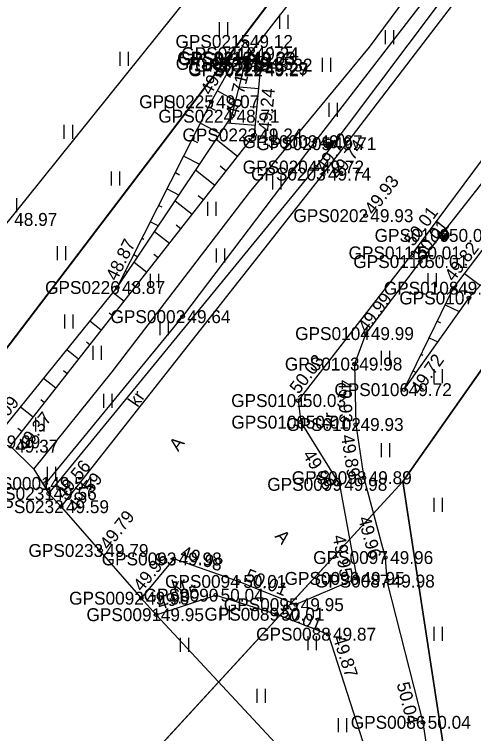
# Model space of a CAD drawing. Extents: x 563121 to 567545, y 6570841 to 6581299.
# Drawn here: x 565782.48 to 565807.43, y 6571805.07 to 6571844.15 of the extents above; entities that cross this region are included whole.
import ezdxf

# ---------------------------------------------------------------- set-up
doc = ezdxf.new("R2010")
doc.units = 0
for name, color, linetype in [('HALJASTUS', 7, 'Continuous'), ('KORGUS-EH2000', 7, 'Continuous'), ('MOOTKORG-EH2000', 7, 'Continuous'), ('MOOTMPUNKT', 7, 'Continuous'), ('MOOTNR', 7, 'Continuous'), ('MOOTPIIR', 7, 'Continuous'), ('PIIR', 7, 'Continuous'), ('POST', 7, 'Continuous'), ('RELJEEF', 7, 'Continuous'), ('SITRASS', 7, 'Continuous'), ('TEE', 7, 'Continuous'), ('TRUUP', 7, 'Continuous')]:
    doc.layers.add(name, color=color, linetype=linetype)

msp = doc.modelspace()

# ---------------------------------------------------------------- linework, layer by layer
at = {"layer": 'HALJASTUS'}
for p, q in [((565796.879, 6571844.119), (565796.879, 6571843.357)), ((565797.334, 6571844.119), (565797.334, 6571843.357)), ((565793.597, 6571843.716), (565793.597, 6571842.955)), ((565794.052, 6571843.716), (565794.052, 6571842.955)), ((565802.616, 6571843.299), (565802.616, 6571842.538)), ((565803.071, 6571843.299), (565803.071, 6571842.538)), ((565788.204, 6571842.119), (565788.204, 6571841.358)), ((565788.659, 6571842.119), (565788.659, 6571841.358)), ((565799.2, 6571841.795), (565799.2, 6571841.034)), ((565799.655, 6571841.795), (565799.655, 6571841.034)), ((565790.667, 6571839.664), (565790.667, 6571838.903)), ((565791.122, 6571839.664), (565791.122, 6571838.903)), ((565799.557, 6571839.345), (565799.557, 6571838.583)), ((565800.012, 6571839.345), (565800.012, 6571838.583)), ((565785.173, 6571838.143), (565785.173, 6571837.382)), ((565785.628, 6571838.143), (565785.628, 6571837.382)), ((565796.096, 6571837.876), (565796.096, 6571837.115)), ((565796.551, 6571837.876), (565796.551, 6571837.115)), ((565787.738, 6571835.612), (565787.738, 6571834.851)), ((565788.193, 6571835.612), (565788.193, 6571834.851)), ((565796.498, 6571835.39), (565796.498, 6571834.628)), ((565796.953, 6571835.39), (565796.953, 6571834.628)), ((565782.597, 6571834.166), (565782.597, 6571833.405)), ((565792.978, 6571833.966), (565792.978, 6571833.205)), ((565793.433, 6571833.966), (565793.433, 6571833.205)), ((565784.809, 6571831.56), (565784.809, 6571830.799)), ((565785.264, 6571831.56), (565785.264, 6571830.799)), ((565793.439, 6571831.435), (565793.439, 6571830.674)), ((565793.894, 6571831.435), (565793.894, 6571830.674)), ((565789.861, 6571830.057), (565789.861, 6571829.296)), ((565790.316, 6571830.057), (565790.316, 6571829.296)), ((565804.948, 6571830.093), (565804.948, 6571829.332)), ((565805.403, 6571830.093), (565805.403, 6571829.332)), ((565785.198, 6571827.84), (565785.198, 6571827.079)), ((565785.653, 6571827.84), (565785.653, 6571827.079)), ((565790.38, 6571827.48), (565790.38, 6571826.719)), ((565790.835, 6571827.48), (565790.835, 6571826.719)), ((565786.743, 6571826.148), (565786.743, 6571825.387)), ((565787.199, 6571826.148), (565787.199, 6571825.387)), ((565802.404, 6571825.86), (565802.404, 6571825.099)), ((565802.859, 6571825.86), (565802.859, 6571825.099)), ((565805.272, 6571824.881), (565805.272, 6571824.119)), ((565805.728, 6571824.881), (565805.728, 6571824.119)), ((565787.32, 6571823.525), (565787.32, 6571822.764)), ((565787.775, 6571823.525), (565787.775, 6571822.764)), ((565783.626, 6571822.239), (565783.626, 6571821.478)), ((565784.081, 6571822.239), (565784.081, 6571821.478)), ((565802.404, 6571820.86), (565802.404, 6571820.099)), ((565802.859, 6571820.86), (565802.859, 6571820.099)), ((565784.261, 6571819.57), (565784.261, 6571818.809)), ((565784.716, 6571819.57), (565784.716, 6571818.809)), ((565805.272, 6571817.881), (565805.272, 6571817.119)), ((565805.728, 6571817.881), (565805.728, 6571817.119)), ((565793.701, 6571812.012), (565793.701, 6571811.251)), ((565794.157, 6571812.012), (565794.157, 6571811.251)), ((565805.272, 6571810.881), (565805.272, 6571810.119)), ((565805.728, 6571810.881), (565805.728, 6571810.119)), ((565791.49, 6571810.282), (565791.49, 6571809.521)), ((565791.945, 6571810.282), (565791.945, 6571809.521)), ((565798.42, 6571810.359), (565798.42, 6571809.598)), ((565798.876, 6571810.359), (565798.876, 6571809.598)), ((565795.645, 6571807.502), (565795.645, 6571806.74)), ((565796.1, 6571807.502), (565796.1, 6571806.74)), ((565800.068, 6571805.911), (565800.068, 6571805.15)), ((565800.523, 6571805.911), (565800.523, 6571805.15))]:
    msp.add_line(p, q, dxfattribs=at)
at = {"layer": 'KORGUS-EH2000'}
for centre in [(565793.178, 6571839.402), (565794.289, 6571838.617), (565795.529, 6571837.598), (565798.874, 6571835.854), (565799.254, 6571835.472), (565801.558, 6571833.212), (565804.137, 6571831.188), (565804.535, 6571830.717), (565788.065, 6571829.31), (565806.328, 6571829.271), (565807.174, 6571828.74), (565801.583, 6571826.805), (565803.644, 6571823.76), (565797.898, 6571823.166), (565801.025, 6571821.866), (565801.467, 6571818.976), (565800.139, 6571818.615), (565784.347, 6571818.115), (565785.017, 6571817.401), (565787.162, 6571815.021), (565802.633, 6571814.638), (565791.141, 6571814.563), (565801.078, 6571813.504), (565794.654, 6571813.34), (565789.374, 6571812.429), (565790.175, 6571811.534), (565796.721, 6571811.558), (565799.531, 6571810.473), (565804.674, 6571805.685)]:
    msp.add_circle(centre, 0.1, dxfattribs=at)
at = {"layer": 'MOOTMPUNKT'}
for centre in [(565795.011, 6571842.678), (565795.327, 6571842.011), (565795.106, 6571841.78), (565795.165, 6571841.732), (565795.026, 6571841.487), (565795.832, 6571841.206), (565796.074, 6571841.393), (565795.847, 6571841.134), (565793.178, 6571839.402), (565794.289, 6571838.617), (565795.529, 6571837.598), (565798.797, 6571837.231), (565799.543, 6571837.122), (565798.874, 6571835.854), (565799.254, 6571835.472), (565801.558, 6571833.212), (565805.83, 6571832.14), (565804.137, 6571831.188), (565804.535, 6571830.717), (565788.065, 6571829.31), (565806.328, 6571829.271), (565807.174, 6571828.74), (565791.619, 6571827.726), (565801.583, 6571826.805), (565800.955, 6571825.15), (565803.644, 6571823.76), (565797.898, 6571823.166), (565798.048, 6571821.994), (565801.025, 6571821.866), (565801.467, 6571818.976), (565784.171, 6571818.664), (565800.139, 6571818.615), (565784.347, 6571818.115), (565785.017, 6571817.401), (565787.162, 6571815.021), (565802.633, 6571814.638), (565791.141, 6571814.563), (565801.078, 6571813.504), (565794.654, 6571813.34), (565802.718, 6571813.36), (565789.374, 6571812.429), (565793.422, 6571812.595), (565797.777, 6571812.08), (565790.175, 6571811.534), (565796.721, 6571811.558), (565799.531, 6571810.473), (565804.674, 6571805.685)]:
    msp.add_circle(centre, 0.1, dxfattribs=at)
at = {"layer": 'MOOTPIIR'}
msp.add_lwpolyline([(565823.283, 6571871.288), (565820.939, 6571873.864), (565815.364, 6571875.639), (565813.463, 6571874.16), (565808.89, 6571868.083), (565802.021, 6571858.377), (565795.67, 6571849.773), (565782.207, 6571833.008), (565776.308, 6571825.832), (565781.278, 6571820.922), (565782.262, 6571820.691), (565783.542, 6571819.443), (565784.347, 6571818.115), (565785.017, 6571817.401), (565789.374, 6571812.429), (565790.175, 6571811.534), (565801.221, 6571799.668)], dxfattribs=at)
at = {"layer": 'PIIR'}
for points in [[(566138.88, 6572289.1), (566071.95, 6572189.53), (566056.92, 6572168.48), (566043.44, 6572149.59), (566020.47, 6572117.41), (565845.87, 6571876.56), (565833.02, 6571860.66), (565803.59, 6571818.77), (565766.84, 6571778.8), (565712.27, 6571733.72), (565636.36, 6571689.97), (565561.65, 6571658.97), (565400, 6571600), (565315, 6571572), (565230, 6571552), (564980, 6571552), (564921.56, 6571543.26)], [(564959.63, 6571567.88), (565247.22, 6571575.87), (565310, 6571592), (565385.09, 6571617.94), (565603.34, 6571696.36), (565663.71, 6571724.88), (565720.01, 6571762.52), (565767.05, 6571806.3), (565831.51, 6571891.07), (565894.85, 6571978.6), (565929.68, 6572026.82), (566028.25, 6572163.26), (566043.71, 6572184.75), (566068.58, 6572219.3), (566114.67, 6572283.35)]]:
    msp.add_lwpolyline(points, dxfattribs=at)
for points in [[(565385.09, 6571617.94), (565348.3, 6571706.93), (565808.88, 6572174.3), (565817.95, 6572187.54), (565914.67, 6572223.63), (565927.34, 6572201.79), (566013.66, 6572213.36), (566028.25, 6572163.26), (565929.68, 6572026.82), (565869.35, 6572071.5), (565833.75, 6572019.48), (565773.79, 6571931.89), (565831.51, 6571891.07), (565767.05, 6571806.3), (565720.01, 6571762.52), (565663.71, 6571724.88), (565603.34, 6571696.36)], [(565833.02, 6571860.66), (565851.06, 6571859.65), (565901.01, 6571846.54), (565960.44, 6571833.78), (565973.49, 6571828.72), (566023.53, 6571796.39), (566089.86, 6571753.57), (566110.96, 6571742.32), (566147.53, 6571725.81), (566160.83, 6571717.7), (565835.49, 6571610.61), (565803.59, 6571818.77)], [(565803.59, 6571818.77), (565835.49, 6571610.61), (565859.22, 6571454.59), (565609.76, 6571322.76), (565540, 6571330), (565490, 6571465), (565440, 6571540), (565400, 6571600), (565561.65, 6571658.97), (565636.36, 6571689.97), (565712.27, 6571733.72), (565766.84, 6571778.8)]]:
    msp.add_lwpolyline(points, close=True, dxfattribs=at)
at = {"layer": 'POST'}
for p, q in [((565799.366, 6571836.946), (565799.719, 6571837.299)), ((565805.653, 6571831.964), (565806.007, 6571832.317))]:
    msp.add_line(p, q, dxfattribs=at)
for centre in [(565799.543, 6571837.122), (565805.83, 6571832.14)]:
    msp.add_circle(centre, 0.25, dxfattribs=at)
for centre, radius, start, end in [((565799.543, 6571837.122), 0.225, 224.8541, 45.0356), ((565799.543, 6571837.122), 0.2, 224.8427, 45.047), ((565799.543, 6571837.122), 0.175, 224.8281, 45.0616), ((565799.543, 6571837.122), 0.15, 224.8087, 45.081), ((565799.543, 6571837.122), 0.125, 224.7814, 45.1083), ((565799.543, 6571837.122), 0.1, 224.7406, 45.1491), ((565799.543, 6571837.122), 0.075, 224.6725, 45.2172), ((565799.543, 6571837.122), 0.05, 224.5363, 45.3534), ((565799.543, 6571837.122), 0.025, 224.1278, 45.7619), ((565805.83, 6571832.14), 0.225, 224.8541, 45.0356), ((565805.83, 6571832.14), 0.2, 224.8427, 45.047), ((565805.83, 6571832.14), 0.175, 224.8281, 45.0616), ((565805.83, 6571832.14), 0.15, 224.8087, 45.081), ((565805.83, 6571832.14), 0.125, 224.7814, 45.1083), ((565805.83, 6571832.14), 0.1, 224.7406, 45.1491), ((565805.83, 6571832.14), 0.075, 224.6725, 45.2172), ((565805.83, 6571832.14), 0.05, 224.5363, 45.3534), ((565805.83, 6571832.14), 0.025, 224.1278, 45.7619)]:
    msp.add_arc(centre, radius, start, end, dxfattribs=at)
at = {"layer": 'RELJEEF'}
for p, q in [((565794.49, 6571841.746), (565795.017, 6571841.451)), ((565794.001, 6571840.873), (565794.229, 6571840.746)), ((565795.843, 6571841.093), (565795.574, 6571841.117)), ((565795.754, 6571840.097), (565794.694, 6571840.192)), ((565793.513, 6571840.001), (565794.503, 6571839.447)), ((565793.036, 6571839.122), (565793.393, 6571838.941)), ((565795.664, 6571839.101), (565795.298, 6571839.134)), ((565792.585, 6571838.23), (565793.665, 6571837.683)), ((565795.575, 6571838.105), (565794.04, 6571838.243)), ((565794.609, 6571836.425), (565793.438, 6571837.344)), ((565795.226, 6571837.212), (565794.857, 6571837.502)), ((565792.133, 6571837.338), (565792.424, 6571837.19)), ((565791.681, 6571836.446), (565792.545, 6571836.008)), ((565793.991, 6571835.639), (565793.658, 6571835.9)), ((565791.229, 6571835.554), (565791.455, 6571835.439)), ((565793.374, 6571834.852), (565792.323, 6571835.677)), ((565790.777, 6571834.662), (565791.425, 6571834.333)), ((565792.757, 6571834.065), (565792.459, 6571834.298)), ((565792.139, 6571833.278), (565791.208, 6571834.009)), ((565790.325, 6571833.77), (565790.487, 6571833.688)), ((565789.873, 6571832.878), (565790.305, 6571832.659)), ((565791.522, 6571832.492), (565791.26, 6571832.697)), ((565790.905, 6571831.705), (565790.093, 6571832.342)), ((565789.421, 6571831.986), (565789.518, 6571831.936)), ((565788.969, 6571831.094), (565789.185, 6571830.984)), ((565790.287, 6571830.918), (565790.062, 6571831.095)), ((565789.67, 6571830.132), (565788.978, 6571830.675)), ((565788.517, 6571830.202), (565788.549, 6571830.185)), ((565806.936, 6571830.07), (565807.798, 6571829.415)), ((565789.053, 6571829.345), (565788.863, 6571829.494)), ((565806.331, 6571829.274), (565806.569, 6571829.093)), ((565788.435, 6571828.558), (565787.837, 6571829.028)), ((565805.892, 6571828.376), (565806.653, 6571828.005)), ((565787.818, 6571827.772), (565787.635, 6571827.915)), ((565787.2, 6571826.985), (565786.579, 6571827.473)), ((565805.454, 6571827.477), (565805.638, 6571827.387)), ((565805.016, 6571826.578), (565805.481, 6571826.351)), ((565786.583, 6571826.198), (565786.393, 6571826.347)), ((565785.966, 6571825.412), (565785.32, 6571825.918)), ((565804.579, 6571825.679), (565804.674, 6571825.632)), ((565785.348, 6571824.625), (565785.151, 6571824.78)), ((565804.141, 6571824.779), (565804.309, 6571824.698)), ((565784.731, 6571823.838), (565784.062, 6571824.363)), ((565784.114, 6571823.051), (565783.91, 6571823.212)), ((565783.496, 6571822.265), (565782.804, 6571822.808)), ((565782.879, 6571821.478), (565782.668, 6571821.644))]:
    msp.add_line(p, q, dxfattribs=at)
for points in [[(565844.04, 6571859.801), (565839.307, 6571861.411), (565835.818, 6571862.396), (565833.848, 6571861.926), (565831.495, 6571861.254), (565830.033, 6571859.153), (565819.486, 6571846.581), (565806.328, 6571829.271), (565803.644, 6571823.76)], [(565830.061, 6571854.393), (565821.897, 6571844.686), (565807.174, 6571828.74), (565803.644, 6571823.76)], [(565788.065, 6571829.31), (565793.178, 6571839.402), (565795.011, 6571842.678), (565795.409, 6571841.942)], [(565781.278, 6571820.922), (565788.065, 6571829.31), (565794.289, 6571838.617), (565795.026, 6571841.487)], [(565782.262, 6571820.691), (565795.529, 6571837.598), (565795.847, 6571841.134), (565795.788, 6571841.243)]]:
    msp.add_lwpolyline(points, dxfattribs=at)
at = {"layer": 'SITRASS'}
for points in [[(565827.937, 6571875.522), (565819.589, 6571864.258), (565813.931, 6571856.898), (565805.842, 6571846.363), (565798.797, 6571837.231), (565791.619, 6571827.726), (565784.171, 6571818.664)], [(565783.542, 6571819.443), (565787.788, 6571824.729), (565795.262, 6571834.475), (565801.765, 6571842.375), (565808.482, 6571851.414), (565811.284, 6571854.993), (565814.22, 6571858.353), (565815.357, 6571859.794), (565816.36, 6571859.39), (565822.04, 6571867.24), (565823.485, 6571869.196), (565824.591, 6571870.729)]]:
    msp.add_lwpolyline(points, dxfattribs=at)
at = {"layer": 'TEE'}
for points in [[(565784.347, 6571818.115), (565798.874, 6571835.854), (565810.584, 6571851.423), (565821.499, 6571866.441), (565824.465, 6571870.379)], [(565785.017, 6571817.401), (565799.254, 6571835.472), (565811.058, 6571850.919), (565822.074, 6571865.705), (565825.255, 6571869.896)], [(565839.194, 6571863.521), (565833.439, 6571863.766), (565828.407, 6571862.073), (565825.907, 6571860.285), (565817.092, 6571848.675), (565804.137, 6571831.188), (565797.898, 6571823.166), (565798.048, 6571821.994), (565800.139, 6571818.615), (565801.078, 6571813.504), (565797.777, 6571812.08), (565794.654, 6571813.34), (565791.141, 6571814.563), (565789.374, 6571812.429)], [(565833.439, 6571863.766), (565828.71, 6571861.712), (565827.373, 6571860.217), (565817.957, 6571847.828), (565804.535, 6571830.717), (565801.583, 6571826.805), (565800.955, 6571825.15), (565801.025, 6571821.866), (565801.467, 6571818.976), (565802.633, 6571814.638), (565802.718, 6571813.36), (565804.674, 6571805.685), (565807.231, 6571788.975), (565811.315, 6571764.792), (565815.474, 6571739.551), (565820.53, 6571709.209), (565821.038, 6571705.752), (565823.803, 6571687.466)], [(565790.175, 6571811.534), (565793.422, 6571812.595), (565796.721, 6571811.558), (565799.531, 6571810.473), (565801.404, 6571804.635), (565804.547, 6571788.369), (565808.49, 6571764.266), (565812.602, 6571739.162), (565817.858, 6571706.273), (565820.638, 6571687.064)]]:
    msp.add_lwpolyline(points, dxfattribs=at)
at = {"layer": 'TRUUP'}
for p, q in [((565795.106, 6571841.78), (565800.195, 6571848.355)), ((565795.167, 6571841.86), (565794.395, 6571841.762)), ((565794.413, 6571841.62), (565794.395, 6571841.762)), ((565794.401, 6571841.72), (565794.416, 6571841.764)), ((565795.106, 6571841.78), (565794.404, 6571841.691)), ((565794.408, 6571841.665), (565794.444, 6571841.768)), ((565795.044, 6571841.701), (565794.413, 6571841.62)), ((565794.419, 6571841.621), (565794.472, 6571841.771)), ((565794.446, 6571841.625), (565794.5, 6571841.775)), ((565794.474, 6571841.628), (565794.527, 6571841.779)), ((565794.502, 6571841.632), (565794.555, 6571841.782)), ((565794.53, 6571841.635), (565794.583, 6571841.786)), ((565794.558, 6571841.639), (565794.611, 6571841.789)), ((565794.585, 6571841.642), (565794.638, 6571841.793)), ((565794.613, 6571841.646), (565794.666, 6571841.796)), ((565794.641, 6571841.649), (565794.694, 6571841.8)), ((565794.669, 6571841.653), (565794.722, 6571841.803)), ((565794.696, 6571841.657), (565794.75, 6571841.807)), ((565794.724, 6571841.66), (565794.777, 6571841.81)), ((565794.752, 6571841.664), (565794.805, 6571841.814)), ((565794.78, 6571841.667), (565794.833, 6571841.817)), ((565794.807, 6571841.671), (565794.861, 6571841.821)), ((565794.835, 6571841.674), (565794.888, 6571841.824)), ((565794.863, 6571841.678), (565794.916, 6571841.828)), ((565794.891, 6571841.681), (565794.944, 6571841.832)), ((565794.919, 6571841.685), (565794.972, 6571841.835)), ((565794.946, 6571841.688), (565794.999, 6571841.839)), ((565794.974, 6571841.692), (565795.027, 6571841.842)), ((565795.002, 6571841.695), (565795.055, 6571841.846)), ((565795.03, 6571841.699), (565795.083, 6571841.849)), ((565795.124, 6571841.07), (565795.044, 6571841.701)), ((565795.047, 6571841.674), (565795.111, 6571841.853)), ((565795.054, 6571841.619), (565795.138, 6571841.856)), ((565795.061, 6571841.564), (565795.166, 6571841.86)), ((565795.068, 6571841.509), (565795.174, 6571841.807)), ((565795.075, 6571841.454), (565795.181, 6571841.752)), ((565795.082, 6571841.399), (565795.188, 6571841.697)), ((565795.089, 6571841.344), (565795.195, 6571841.642)), ((565795.195, 6571841.079), (565795.106, 6571841.78)), ((565795.266, 6571841.088), (565795.167, 6571841.86)), ((565795.096, 6571841.288), (565795.202, 6571841.587)), ((565795.104, 6571841.233), (565795.209, 6571841.532)), ((565795.111, 6571841.178), (565795.216, 6571841.476)), ((565795.118, 6571841.123), (565795.223, 6571841.421)), ((565795.125, 6571841.07), (565795.23, 6571841.366)), ((565795.153, 6571841.074), (565795.237, 6571841.311)), ((565795.181, 6571841.077), (565795.244, 6571841.256)), ((565795.124, 6571841.07), (565795.266, 6571841.088)), ((565795.209, 6571841.081), (565795.251, 6571841.201)), ((565795.236, 6571841.084), (565795.258, 6571841.146))]:
    msp.add_line(p, q, dxfattribs=at)
msp.add_lwpolyline([(565795.327, 6571842.011), (565796.074, 6571841.393), (565795.884, 6571841.163), (565795.137, 6571841.781)], close=True, dxfattribs=at)

# ---------------------------------------------------------------- texts
at = {"layer": 'KORGUS-EH2000'}
for s, rotation, p in [(' 49.07', 60.7788, (565793.026, 6571839.487)), (' 48.71', 75.606, (565794.547, 6571838.276)), (' 49.24', 84.8633, (565796.401, 6571837.52)), (' 49.72', 53.0515, (565799.188, 6571835.301)), (' 49.74', 52.6147, (565799.949, 6571834.941)), (' 49.93', 52.5569, (565801.836, 6571832.999)), (' 50.01', 53.469, (565803.996, 6571831.292)), (' 50.01', 51.8886, (565804.524, 6571830.603)), (' 48.87', 63.1292, (565787.909, 6571829.389)), (' 49.82', 52.7605, (565806.188, 6571829.377)), (' 49.99', 52.9613, (565801.475, 6571826.609)), (' 50.03', 52.1269, (565797.76, 6571823.273)), (' 49.72', 54.6728, (565804.358, 6571823.254)), (' 49.93', 271.2353, (565800.09, 6571824.545)), (' 49.09', 51.0237, (565781.142, 6571821.032)), (' 49.37', 51.8773, (565782.95, 6571820.151)), (' 49.89', 278.6872, (565800.188, 6571821.522)), (' 49.98', 301.7476, (565797.977, 6571820.445)), (' 49.56', 50.685, (565785.024, 6571817.56)), (' 49.59', 51.7673, (565785.704, 6571816.859)), (' 49.79', 51.6426, (565787.436, 6571814.804)), (' 49.96', 285.0395, (565801.082, 6571817.025)), (' 49.95', 280.4135, (565799.721, 6571816.058)), (' 49.98', 340.808, (565791.199, 6571814.728)), (' 49.96', 50.3657, (565789.239, 6571812.541)), (' 50.01', 338.0321, (565794.719, 6571813.502)), (' 49.95', 18.0875, (565790.12, 6571811.701)), (' 50.01', 338.8939, (565796.59, 6571811.568)), (' 49.87', 287.7886, (565799.698, 6571810.526)), (' 50.04', 284.2944, (565803.178, 6571808.029))]:
    msp.add_text(s, height=0.7, rotation=rotation, dxfattribs=at).set_placement(p)
msp.add_text(' 48.97', height=0.7, dxfattribs=at).set_placement((565782.207, 6571832.658))
at = {"layer": 'MOOTKORG-EH2000'}
for s, p in [(' 49.12', (565795.011, 6571842.328)), (' 49.05', (565795.106, 6571841.43)), (' 49.23', (565795.165, 6571841.382)), (' 49.24', (565795.327, 6571841.661)), (' 48.65', (565795.026, 6571841.137)), (' 49.32', (565796.074, 6571841.043)), (' 49.29', (565795.832, 6571840.856)), (' 49.27', (565795.847, 6571840.784)), (' 49.07', (565793.178, 6571839.052)), (' 48.71', (565794.289, 6571838.267)), (' 49.24', (565795.529, 6571837.248)), (' 49.67', (565798.797, 6571836.881)), (' 49.71', (565799.543, 6571836.772)), (' 49.72', (565798.874, 6571835.504)), (' 49.74', (565799.254, 6571835.122)), (' 49.93', (565801.558, 6571832.862)), (' 48.97', (565782.207, 6571832.658)), (' 50.03', (565805.83, 6571831.79)), (' 50.01', (565804.137, 6571830.838)), (' 50.01', (565804.535, 6571830.367)), (' 48.87', (565788.065, 6571828.96)), (' 49.82', (565806.328, 6571828.921)), (' 49.64', (565791.619, 6571827.376)), (' 49.99', (565801.583, 6571826.455)), (' 49.98', (565800.955, 6571824.8)), (' 49.72', (565803.644, 6571823.41)), (' 50.03', (565797.898, 6571822.816)), (' 50.01', (565798.048, 6571821.644)), (' 49.93', (565801.025, 6571821.516)), (' 49.09', (565781.278, 6571820.572)), (' 49.37', (565782.262, 6571820.341)), (' 49.54', (565784.171, 6571818.314)), (' 49.89', (565801.467, 6571818.626)), (' 49.98', (565800.139, 6571818.265)), (' 49.56', (565784.347, 6571817.765)), (' 49.59', (565785.017, 6571817.051)), (' 49.79', (565787.162, 6571814.671)), (' 49.98', (565791.141, 6571814.213)), (' 49.96', (565802.633, 6571814.288)), (' 50.01', (565794.654, 6571812.99)), (' 49.95', (565801.078, 6571813.154)), (' 49.98', (565802.718, 6571813.01)), (' 49.96', (565789.374, 6571812.079)), (' 50.04', (565793.422, 6571812.245)), (' 49.95', (565797.777, 6571811.73)), (' 49.95', (565790.175, 6571811.184)), (' 50.01', (565796.721, 6571811.208)), (' 49.87', (565799.531, 6571810.123)), (' 50.04', (565804.674, 6571805.335))]:
    msp.add_text(s, height=0.7, dxfattribs=at).set_placement(p)
at = {"layer": 'MOOTNR'}
for s, p in [('GPS0215 ', (565791.231, 6571842.328)), ('GPS0216 ', (565791.326, 6571841.43)), ('GPS0217 ', (565791.385, 6571841.382)), ('GPS0218 ', (565791.547, 6571841.661)), ('GPS0221 ', (565791.246, 6571841.137)), ('GPS0219 ', (565792.294, 6571841.043)), ('GPS0220 ', (565791.913, 6571840.856)), ('GPS0222 ', (565791.927, 6571840.784)), ('GPS0225 ', (565789.259, 6571839.052)), ('GPS0224 ', (565790.3, 6571838.267)), ('GPS0223 ', (565791.61, 6571837.248)), ('GPS0003 ', (565794.878, 6571836.881)), ('GPS0205 ', (565795.623, 6571836.772)), ('GPS0204 ', (565794.884, 6571835.504)), ('GPS0203 ', (565795.334, 6571835.122)), ('GPS0202 ', (565797.638, 6571832.862)), ('GPS0109 ', (565802.051, 6571831.79)), ('GPS0111 ', (565800.637, 6571830.838)), ('GPS0110 ', (565800.895, 6571830.367)), ('GPS0226 ', (565784.145, 6571828.96)), ('GPS0108 ', (565802.548, 6571828.921)), ('GPS0107 ', (565803.394, 6571828.39)), ('GPS0002 ', (565787.699, 6571827.376)), ('GPS0104 ', (565797.733, 6571826.455)), ('GPS0103 ', (565797.175, 6571824.8)), ('GPS0106 ', (565799.864, 6571823.41)), ('GPS0101 ', (565794.258, 6571822.816)), ('GPS0100 ', (565794.268, 6571821.644)), ('GPS0102 ', (565797.246, 6571821.516)), ('GPS0001 ', (565780.391, 6571818.314)), ('GPS0098 ', (565797.547, 6571818.626)), ('GPS0099 ', (565796.219, 6571818.265)), ('GPS0231 ', (565780.567, 6571817.765)), ('GPS0232 ', (565781.097, 6571817.051)), ('GPS0233 ', (565783.242, 6571814.671)), ('GPS0093 ', (565787.222, 6571814.213)), ('GPS0097 ', (565798.713, 6571814.288)), ('GPS0094 ', (565790.664, 6571812.99)), ('GPS0096 ', (565797.159, 6571813.154)), ('GPS0087 ', (565798.799, 6571813.01)), ('GPS0092 ', (565785.454, 6571812.079)), ('GPS0090 ', (565789.502, 6571812.245)), ('GPS0095 ', (565793.857, 6571811.73)), ('GPS0091 ', (565786.395, 6571811.184)), ('GPS0089 ', (565792.801, 6571811.208)), ('GPS0088 ', (565795.612, 6571810.123)), ('GPS0086 ', (565800.754, 6571805.335))]:
    msp.add_text(s, height=0.7, dxfattribs=at).set_placement(p)
at = {"layer": 'TEE'}
for s, rotation, p in [('kr', 55.1552, (565789.17, 6571822.763)), ('kr', 85.2199, (565799.896, 6571821.711)), ('A', 52.122, (565791.378, 6571820.365)), ('A', 310.9288, (565796.601, 6571815.775)), ('kr', 18.0419, (565791.166, 6571812.711))]:
    msp.add_text(s, height=0.7, rotation=rotation, dxfattribs=at).set_placement(p)

doc.saveas('drawing.dxf')
